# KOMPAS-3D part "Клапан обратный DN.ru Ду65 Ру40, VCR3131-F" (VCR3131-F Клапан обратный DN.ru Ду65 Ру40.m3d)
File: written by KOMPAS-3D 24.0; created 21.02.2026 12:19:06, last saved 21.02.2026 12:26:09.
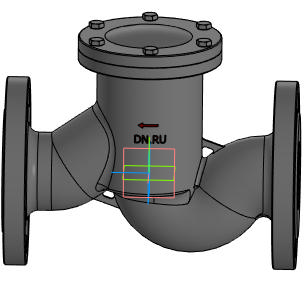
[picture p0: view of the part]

Document properties: Автор: R2D2; Полное имя файла: VCR3131-F Клапан обратный DN.ru Ду65 Ру40.cdw

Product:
- Part/product: Клапан обратный DN.ru Ду65 Ру40  | designation VCR3131-F
    Масса: 15.5
    Раздел спецификации: Прочие изделия
    Форматы листов документа: A2
    Примечание: D100-04042
    additional columns: D100-04042

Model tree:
1. Операция без истории:1

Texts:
  VCR3131-F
